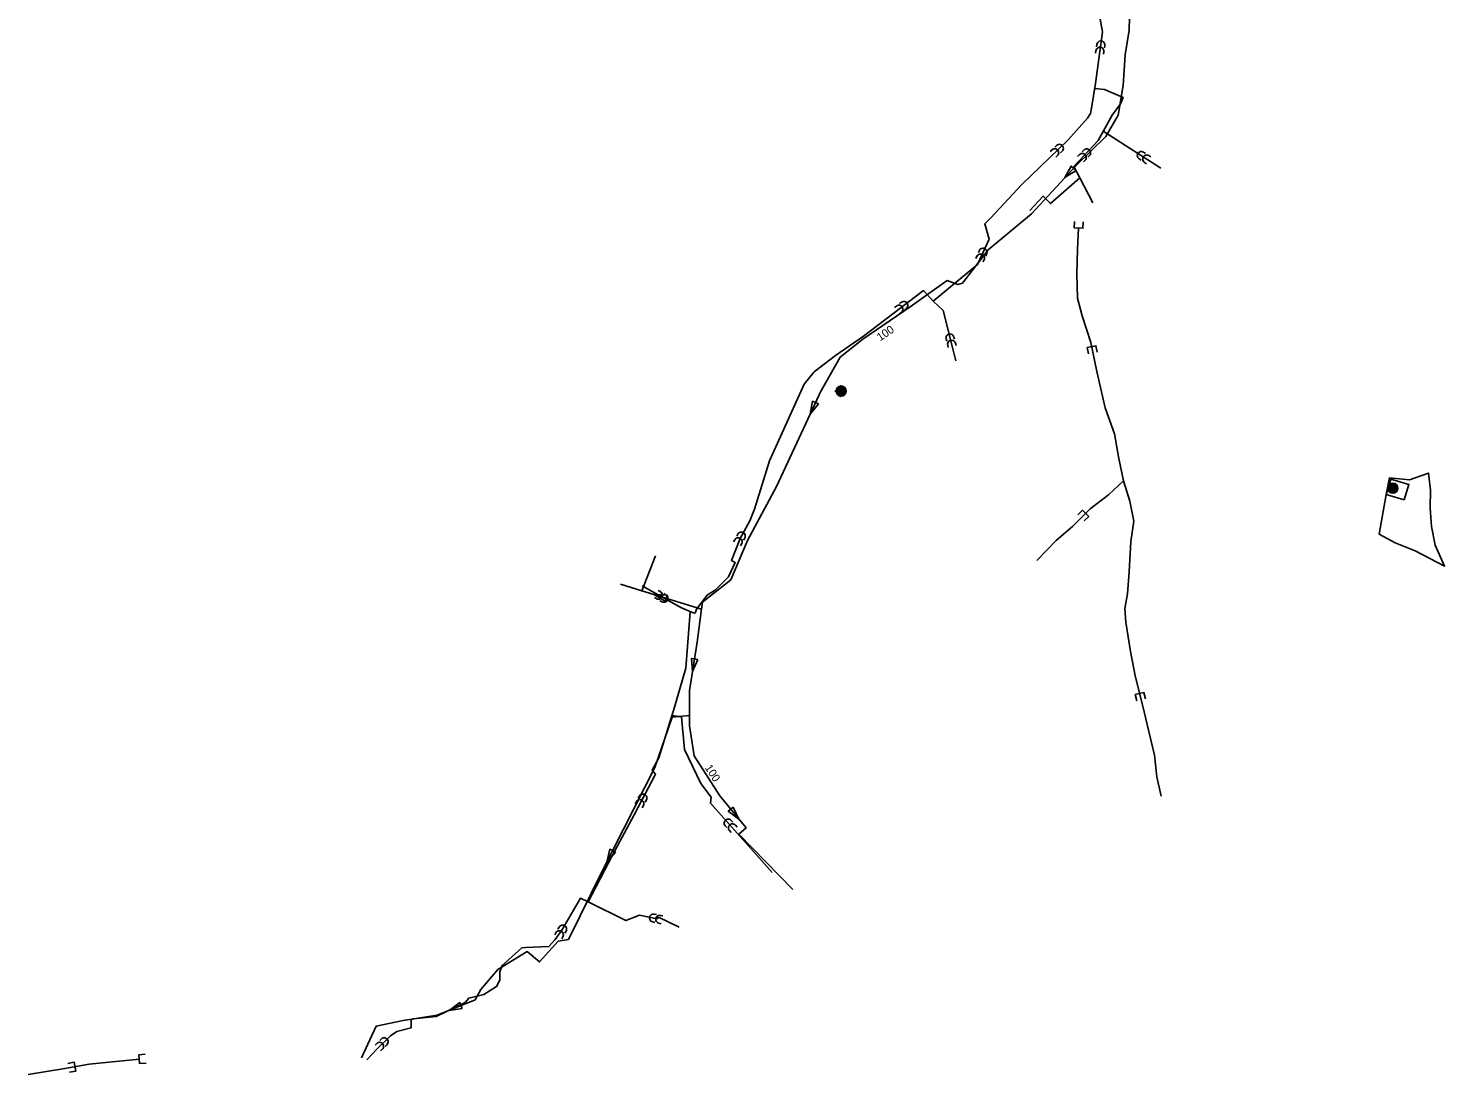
# Model space of a CAD drawing. Extents: x -545007 to -535309, y -1042871 to -1037511.
# Drawn here: x -544982 to -543212, y -1042871 to -1041564 of the extents above; entities that cross this region are included whole.
import ezdxf

# ---------------------------------------------------------------- set-up
doc = ezdxf.new("R2010")
doc.units = 0
for name, color, linetype in [('Vrstva 3', 7, 'Continuous'), ('Vrstva 32', 7, 'Continuous'), ('Vrstva 33', 7, 'Continuous'), ('Vrstva 55', 7, 'Continuous'), ('Vrstva 56', 7, 'Continuous'), ('Vrstva 7', 7, 'Continuous')]:
    doc.layers.add(name, color=color, linetype=linetype)

msp = doc.modelspace()

# ---------------------------------------------------------------- linework, layer by layer
at = {"layer": 'Vrstva 3'}
for points in [[(-543605.2, -1041533.4), (-543606, -1041566.4), (-543610.8, -1041597), (-543613.3, -1041635.6), (-543619.7, -1041672.6), (-543635, -1041699.1), (-543672, -1041735.3), (-543701.8, -1041767.4), (-543728.1, -1041795.6), (-543782.1, -1041840.6), (-543814.2, -1041882.4), (-543819.9, -1041884), (-543833.5, -1041879.2), (-543859, -1041897.5), (-543879.4, -1041912.2), (-543938.9, -1041952.4), (-543967.1, -1041974.9), (-543992, -1042019), (-543993.5, -1042022.1), (-544046.7, -1042136.4), (-544083, -1042203.9), (-544103.9, -1042253), (-544139.3, -1042281.1), (-544140.4, -1042289.8), (-544145.7, -1042331), (-544155.4, -1042391.3), (-544155.4, -1042422.5), (-544155.4, -1042435.5), (-544149.7, -1042473.2), (-544117.5, -1042523), (-544084.6, -1042563.2), (-544093.6, -1042571.1), (-544026.3, -1042640)], [(-544214.8, -1042266.8), (-544197.8, -1042223.2)], [(-544140.4, -1042289.8), (-544214.8, -1042266.8), (-544241.6, -1042258.5)], [(-544155.4, -1042422.5), (-544177.1, -1042424.9), (-544198.8, -1042487.6), (-544264, -1042616.3), (-544306.6, -1042702.4), (-544319.5, -1042704.8), (-544342.8, -1042730.5), (-544358.1, -1042717.6), (-544395.1, -1042740.1), (-544416, -1042765.1), (-544423.3, -1042777.9), (-544470.7, -1042797.2), (-544513.2, -1042803.7), (-544547, -1042810.9), (-544565.5, -1042850.3)]]:
    msp.add_lwpolyline(points, dxfattribs=at)
for points in [[(-543672.3, -1041741.5), (-543678.2, -1041736.1), (-543686.1, -1041750.5)], [(-543994.3, -1042033.3), (-544001.5, -1042029.9), (-544004.7, -1042046.1)], [(-544185.5, -1042280), (-544183.2, -1042272.4), (-544199.6, -1042271.5)], [(-544145.1, -1042352.7), (-544153, -1042351.4), (-544151.6, -1042367.8)], [(-544100.7, -1042537.2), (-544106.9, -1042542.3), (-544093.7, -1042552.1)], [(-544247.9, -1042593.4), (-544255, -1042589.8), (-544258.7, -1042605.9)], [(-544439.5, -1042788.9), (-544442.5, -1042781.4), (-544455.8, -1042791.2)]]:
    msp.add_lwpolyline(points, close=True, dxfattribs=at)
at = {"layer": 'Vrstva 32'}
for p, q in [((-543646.3, -1041584.1), (-543646.7, -1041587)), ((-543636.4, -1041585.4), (-543636.8, -1041588.4)), ((-543647.4, -1041592), (-543647.8, -1041595)), ((-543637.5, -1041593.4), (-543637.9, -1041596.3)), ((-543638.3, -1041692.7), (-543566.1, -1041738.7)), ((-543696.6, -1041710.3), (-543698.7, -1041712.4)), ((-543702.3, -1041715.9), (-543704.5, -1041718)), ((-543695.4, -1041723.1), (-543697.5, -1041725.2)), ((-543689.6, -1041717.5), (-543691.8, -1041719.6)), ((-543668.2, -1041722), (-543670.3, -1041724.2)), ((-543662.7, -1041716.2), (-543664.8, -1041718.3)), ((-543661, -1041728.8), (-543663, -1041731)), ((-543655.5, -1041723), (-543657.5, -1041725.2)), ((-543593.4, -1041727.2), (-543590.9, -1041728.9)), ((-543588, -1041718.8), (-543585.5, -1041720.4)), ((-543586.7, -1041731.5), (-543584.1, -1041733.2)), ((-543581.3, -1041723.1), (-543578.8, -1041724.7)), ((-543667.6, -1041750.8), (-543651.3, -1041782)), ((-543796.4, -1041848.9), (-543797.6, -1041851.6)), ((-543793, -1041841.6), (-543794.3, -1041844.3)), ((-543787.3, -1041853.1), (-543788.6, -1041855.8)), ((-543784, -1041845.8), (-543785.2, -1041848.5)), ((-543890.4, -1041906.2), (-543892.8, -1041908)), ((-543896.8, -1041911), (-543899.1, -1041912.9)), ((-543890.7, -1041919), (-543893.1, -1041920.8)), ((-543884.3, -1041914.2), (-543886.7, -1041916)), ((-543834.6, -1041952.1), (-543833.9, -1041955)), ((-543832.6, -1041959.9), (-543831.9, -1041962.8)), ((-543824.9, -1041949.7), (-543824.2, -1041952.6)), ((-543822.9, -1041957.5), (-543822.2, -1041960.4)), ((-544098.9, -1042203.1), (-544100.3, -1042205.7)), ((-544095, -1042196.1), (-544096.4, -1042198.7)), ((-544090.1, -1042207.9), (-544091.6, -1042210.5)), ((-544086.2, -1042200.9), (-544087.7, -1042203.6)), ((-544196.7, -1042276.6), (-544199.3, -1042275.2)), ((-544191.8, -1042267.9), (-544194.4, -1042266.5)), ((-544189.8, -1042280.6), (-544192.4, -1042279.1)), ((-544184.9, -1042271.8), (-544187.5, -1042270.4)), ((-544218, -1042523.4), (-544219.4, -1042526.1)), ((-544209.2, -1042528.1), (-544210.6, -1042530.8)), ((-544221.8, -1042530.5), (-544223.2, -1042533.1)), ((-544213, -1042535.2), (-544214.4, -1042537.9)), ((-544110.7, -1042560.5), (-544108.7, -1042562.7)), ((-544103.3, -1042553.8), (-544101.3, -1042556.1)), ((-544097.9, -1042559.8), (-544096, -1042562)), ((-544105.4, -1042566.4), (-544103.4, -1042568.7)), ((-544318.3, -1042687.2), (-544319.8, -1042689.8)), ((-544201.4, -1042680.6), (-544198.5, -1042681.2)), ((-544199.4, -1042670.8), (-544196.5, -1042671.4)), ((-544193.6, -1042682.2), (-544190.6, -1042682.8)), ((-544191.6, -1042672.4), (-544188.6, -1042673)), ((-544322.3, -1042694.1), (-544323.8, -1042696.7)), ((-544313.6, -1042699.1), (-544315.1, -1042701.7)), ((-544309.7, -1042692.1), (-544311.1, -1042694.7)), ((-544540.4, -1042826.8), (-544542.6, -1042828.9)), ((-544546.2, -1042832.4), (-544548.4, -1042834.4)), ((-544539.3, -1042839.6), (-544541.4, -1042841.7)), ((-544533.5, -1042834), (-544535.7, -1042836.1))]:
    msp.add_line(p, q, dxfattribs=at)
for points in [[(-543647.7, -1041522.8), (-543639, -1041568.5), (-543648, -1041632.9), (-543653.1, -1041663.9), (-543654.4, -1041670.5), (-543657.9, -1041676.4), (-543668.3, -1041688.1), (-543682.2, -1041703.4), (-543740, -1041759.1), (-543779.1, -1041801.4), (-543786.4, -1041808.3), (-543781, -1041827.5), (-543795.6, -1041859.1), (-543850.7, -1041904.8), (-543862.8, -1041891.6), (-543938.1, -1041948.6), (-543972.7, -1041972.8), (-543999.4, -1041993.3), (-544011.9, -1042008.8), (-544055.3, -1042104.3), (-544074, -1042164.9), (-544080.1, -1042179.6), (-544092.2, -1042201.4), (-544103, -1042229.1), (-544098.1, -1042231.6), (-544106.8, -1042249.2), (-544122.7, -1042265.5), (-544133.4, -1042272.1), (-544146.6, -1042289.7), (-544148.3, -1042294.6), (-544154.6, -1042293.2), (-544160.1, -1042363.5), (-544174.3, -1042412.3), (-544193.9, -1042475.6), (-544202.2, -1042491.1), (-544197.7, -1042496), (-544224.7, -1042546.6), (-544251.5, -1042597.3), (-544282, -1042655.5), (-544291.7, -1042651), (-544314.8, -1042691), (-544323.4, -1042702.4), (-544331, -1042711.4), (-544360.1, -1042712.5), (-544365, -1042712.8), (-544389.6, -1042735), (-544392.3, -1042742.9), (-544392.3, -1042753.3), (-544396.5, -1042761.3), (-544412.4, -1042771.3), (-544431.3, -1042775.7), (-544435.8, -1042781.2), (-544471.8, -1042798.9), (-544500.6, -1042801.6), (-544503.3, -1042803), (-544503.3, -1042813.1), (-544521, -1042817.6), (-544529, -1042822.8), (-544546.3, -1042839.4), (-544558.8, -1042852.9)], [(-543649.1, -1041639.1), (-543636.9, -1041640.5), (-543613.4, -1041650.6), (-543616.9, -1041658.2), (-543627.3, -1041672.7), (-543644.6, -1041704.2), (-543675.2, -1041736.6), (-543667.6, -1041750.8)], [(-543667.6, -1041750.8), (-543704.3, -1041783), (-543713.3, -1041773.7), (-543729.9, -1041791.7)], [(-543850.7, -1041904.8), (-543838.3, -1041916.7), (-543825.9, -1041966.2), (-543822.4, -1041979.4)], [(-544153.6, -1042293.3), (-544165.5, -1042288.2), (-544181.4, -1042279.5), (-544214.7, -1042260.8)], [(-544177.5, -1042422.5), (-544165.3, -1042424.5), (-544161.5, -1042465), (-544141.1, -1042507.8), (-544128.3, -1042524.7), (-544129.2, -1042532.3), (-544051.9, -1042618.9)], [(-544282, -1042655.5), (-544235, -1042678.8), (-544235, -1042678.8), (-544217.7, -1042672.2), (-544217.7, -1042672.2), (-544195.7, -1042676.7), (-544195.7, -1042676.7), (-544194, -1042674.8), (-544194, -1042674.8), (-544168.2, -1042687.3)]]:
    msp.add_lwpolyline(points, dxfattribs=at)
for centre, start, end in [((-543642.4, -1041592.7), 352.0381, 172.0391), ((-543641.3, -1041584.8), 352.0381, 172.0391), ((-543693.1, -1041713.9), 313.951, 133.9521), ((-543698.9, -1041719.5), 313.951, 133.9521), ((-543664.6, -1041725.4), 316.581, 136.5821), ((-543659.1, -1041719.6), 316.581, 136.5821), ((-543590.7, -1041723), 57.4972, 237.4982), ((-543584, -1041727.3), 57.4972, 237.4982), ((-543791.8, -1041851), 335.2214, 155.2225), ((-543788.5, -1041843.7), 335.2214, 155.2225), ((-543887.4, -1041910.2), 307.104, 127.1051), ((-543893.7, -1041915), 307.104, 127.1051), ((-543829.7, -1041950.9), 14.1315, 194.1325), ((-543827.8, -1041958.7), 14.1315, 194.1325), ((-544094.5, -1042205.5), 330.9499, 150.9509), ((-544090.6, -1042198.5), 330.9499, 150.9509), ((-544194.3, -1042272.3), 240.6463, 60.6474), ((-544187.3, -1042276.2), 240.6463, 60.6474), ((-544217.4, -1042532.8), 331.8881, 151.8892), ((-544213.6, -1042525.8), 331.8881, 151.8892), ((-544107, -1042557.1), 41.7405, 221.7415), ((-544101.7, -1042563.1), 41.7405, 221.7415), ((-544314, -1042689.6), 330.0688, 150.0699), ((-544200.4, -1042675.7), 78.4399, 258.4409), ((-544192.6, -1042677.3), 78.4399, 258.4409), ((-544318, -1042696.6), 330.0688, 150.0699), ((-544537, -1042830.4), 313.8522, 133.8533), ((-544542.7, -1042836), 313.8522, 133.8533)]:
    msp.add_arc(centre, 5, start, end, dxfattribs=at)
at = {"layer": 'Vrstva 33'}
for points in [[(-543674.2, -1041805.4), (-543674.6, -1041813.4), (-543663.6, -1041813.9), (-543663.2, -1041805.9)], [(-543669.1, -1041813.7), (-543670.3, -1041840.1), (-543671.2, -1041870.6), (-543670.3, -1041901), (-543664.5, -1041923.2), (-543653.8, -1041956.6), (-543646.3, -1041992.8), (-543635.8, -1042038.4), (-543624.1, -1042070.6), (-543618.6, -1042101.5), (-543612.8, -1042129.3), (-543605, -1042155), (-543600, -1042179.8), (-543603.9, -1042205.1), (-543606, -1042243.2), (-543607.8, -1042270.8), (-543611.3, -1042288.8), (-543609.9, -1042306)], [(-543645.7, -1041968.5), (-543647.4, -1041960.6), (-543658.2, -1041962.9), (-543656.5, -1041970.7)], [(-543612.8, -1042129.3), (-543631.6, -1042146.9), (-543654.7, -1042164.6), (-543676.4, -1042185.9), (-543697, -1042203.9), (-543721.3, -1042229.1)], [(-543662.1, -1042179.6), (-543656.4, -1042174), (-543664.2, -1042166.2), (-543669.9, -1042171.8)], [(-543609.9, -1042306), (-543604.2, -1042342.8), (-543598.4, -1042372.9), (-543589, -1042411), (-543581.3, -1042442.6), (-543574.4, -1042472.3), (-543571.1, -1042499.1), (-543565.7, -1042523.6)], [(-543585.6, -1042401.7), (-543587.5, -1042394), (-543598.2, -1042396.6), (-543596.3, -1042404.4)], [(-544835.7, -1042845.9), (-544843.6, -1042846.7), (-544842.6, -1042857.6), (-544834.6, -1042856.9)], [(-544981.7, -1042871.4), (-544936, -1042863.6), (-544905.6, -1042858.4), (-544868.3, -1042854.6), (-544842.9, -1042852.2)], [(-544930.3, -1042868.2), (-544922.4, -1042866.9), (-544924.3, -1042856), (-544932.2, -1042857.3)]]:
    msp.add_lwpolyline(points, dxfattribs=at)
at = {"layer": 'Vrstva 55'}
for points in [[(-543966.7, -1042024.5), (-543959.3, -1042017.7), (-543966.2, -1042010.4), (-543973.5, -1042017.2), (-543966.7, -1042024.5)], [(-543262.3, -1042153), (-543256.3, -1042133.8), (-543278.8, -1042127.4), (-543284.5, -1042146.3), (-543262.3, -1042153)]]:
    msp.add_lwpolyline(points, dxfattribs=at)
at = {"layer": 'Vrstva 56'}
msp.add_lwpolyline([(-543229.4, -1042141.1), (-543231.8, -1042119.7), (-543255.6, -1042128), (-543280.6, -1042125.7), (-543284.5, -1042146.3), (-543293.3, -1042195.9), (-543273.5, -1042207), (-543248.5, -1042216.9), (-543211.6, -1042236), (-543223.5, -1042209.8), (-543228.2, -1042186.4), (-543229.8, -1042163), (-543229.4, -1042141.1)], dxfattribs=at)
at = {"layer": 'Vrstva 7'}
for centre, radius in [((-543965.9, -1042017.2), 6.3), ((-543965.9, -1042017.2), 5.3), ((-543965.9, -1042017.2), 4.3), ((-543965.9, -1042017.2), 3.3), ((-543965.9, -1042017.2), 2.3), ((-543965.9, -1042017.2), 1.3), ((-543965.9, -1042017.2), 0.3), ((-543276.3, -1042138.6), 6.3), ((-543276.3, -1042138.6), 5.3), ((-543276.3, -1042138.6), 4.3), ((-543276.3, -1042138.6), 3.3), ((-543276.3, -1042138.6), 2.3), ((-543276.3, -1042138.6), 1.3), ((-543276.3, -1042138.6), 0.3)]:
    msp.add_circle(centre, radius, dxfattribs=at)

# ---------------------------------------------------------------- texts
at = {"layer": 'Vrstva 3'}
for rotation, p in [(34.033, (-543917.1, -1041955.2)), (302.841, (-544136.7, -1042487.8))]:
    msp.add_text('100', height=10, rotation=rotation, dxfattribs=at).set_placement(p)

doc.saveas('drawing.dxf')
